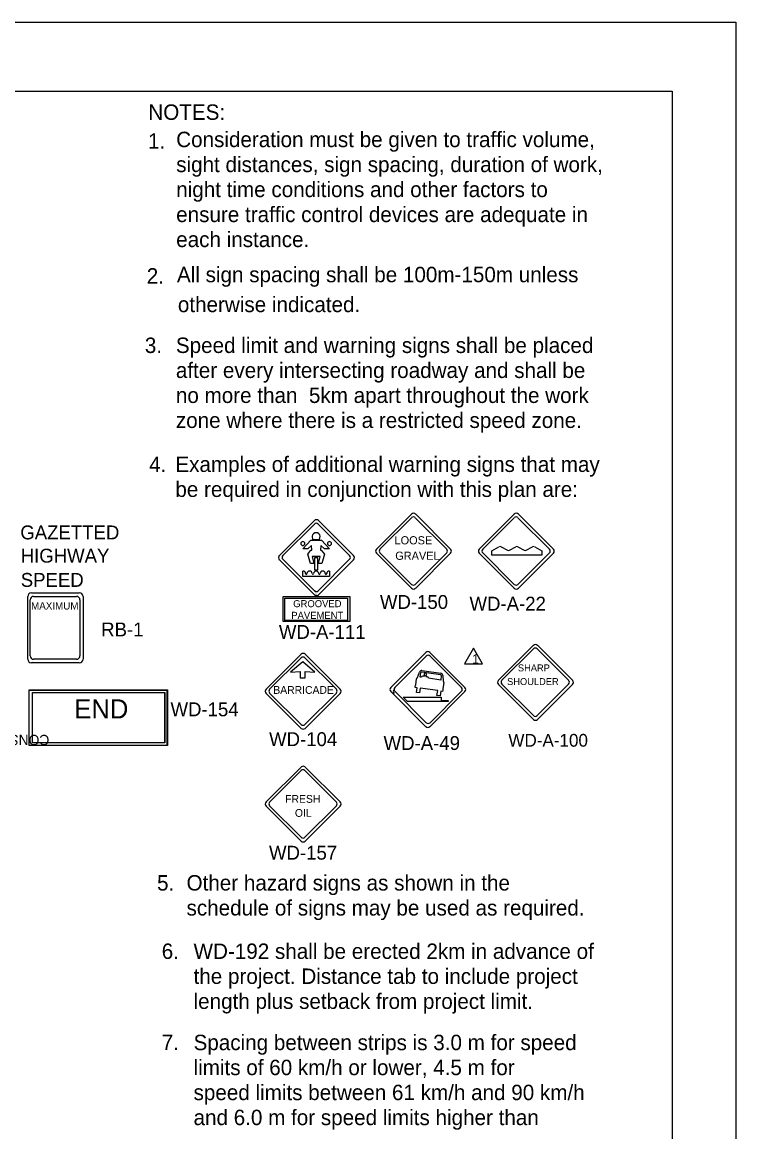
# Model space of a CAD drawing. Extents: x 1372 to 1588, y 125 to 404.
# Drawn here: x 1476.2 to 1588.1, y 229.9 to 404 of the extents above; entities that cross this region are included whole.
import ezdxf

# ---------------------------------------------------------------- set-up
doc = ezdxf.new("R2010")
doc.units = 0
for name, color, linetype in [('Level 1', 7, 'Continuous'), ('Level 10', 7, 'Continuous'), ('Level 2', 7, 'Continuous'), ('Level 4', 7, 'Continuous'), ('Level 44', 7, 'Continuous'), ('Level 5', 7, 'Continuous'), ('Level 60', 7, 'Continuous')]:
    doc.layers.add(name, color=color, linetype=linetype)

msp = doc.modelspace()

# ---------------------------------------------------------------- linework, layer by layer
at = {"layer": 'Level 1'}
for p, q in [((1549.79, 321.06), (1550.93, 321.68)), ((1549.79, 320.37), (1549.79, 321.06)), ((1553.73, 320.37), (1549.79, 320.37)), ((1551.27, 321.68), (1552.25, 321.14)), ((1552.58, 321.14), (1553.56, 321.68)), ((1557.67, 320.37), (1553.73, 320.37)), ((1553.9, 321.68), (1554.87, 321.15)), ((1555.21, 321.15), (1556.19, 321.68)), ((1556.53, 321.68), (1557.67, 321.07)), ((1557.67, 321.07), (1557.67, 320.37)), ((1538.05, 301.1), (1538.16, 301.17)), ((1538.16, 301.17), (1538.47, 302.04)), ((1538.55, 301.26), (1538.7, 301.96)), ((1538.77, 301.22), (1538.55, 301.26)), ((1538.84, 302.28), (1541.83, 301.85)), ((1538.86, 302.06), (1541.75, 301.65)), ((1539.16, 301.38), (1539.01, 301.4)), ((1539.01, 301.4), (1539.01, 301.4)), ((1539.69, 301.3), (1539.54, 301.32)), ((1541.86, 301.51), (1541.83, 300.79)), ((1542.12, 301.53), (1542.17, 300.6)), ((1537.81, 299.62), (1537.81, 299.9)), ((1538.09, 299.59), (1537.81, 299.62)), ((1537.9, 300.03), (1538, 300.99)), ((1537.98, 298.84), (1538.09, 299.59)), ((1538.59, 299.52), (1538.48, 298.77)), ((1541.33, 299.13), (1538.59, 299.52)), ((1541.83, 300.79), (1539.87, 301.07)), ((1542.28, 300.39), (1542.11, 299.42)), ((1542.17, 300.6), (1542.26, 300.5)), ((1538.48, 298.77), (1537.98, 298.84)), ((1541.21, 298.38), (1541.33, 299.13)), ((1541.71, 298.31), (1541.21, 298.38)), ((1541.83, 299.06), (1541.71, 298.31)), ((1542.08, 299.02), (1541.83, 299.05)), ((1542.15, 299.28), (1542.08, 299.02)), ((1542.13, 299.32), (1542.15, 299.28))]:
    msp.add_line(p, q, dxfattribs=at)
for points in [[(1546.94, 305.79), (1545.52, 303.32), (1548.36, 303.32)], [(1542.95, 297.41), (1536.61, 297.41), (1535.92, 298.1), (1541.86, 298.1), (1541.86, 297.58), (1542.95, 297.58)]]:
    msp.add_lwpolyline(points, close=True, dxfattribs=at)
for centre, radius, start, end in [((1551.1, 321.37), 0.35, 61.3649, 118.2462), ((1552.41, 321.45), 0.35, 241.3895, 298.4822), ((1553.73, 321.37), 0.35, 61.6364, 118.4879), ((1555.04, 321.46), 0.35, 241.6262, 298.2462), ((1556.36, 321.37), 0.35, 61.8639, 118.2174), ((1538.79, 301.93), 0.344, 81.9388, 160.7571), ((1538.84, 301.92), 0.138, 81.9344, 167.2438), ((1538.98, 301.2), 0.206, 81.9281, 171.9074), ((1539.17, 301.45), 0.0688, 261.9205, 351.8582), ((1539.55, 301.39), 0.0688, 171.8828, 261.9459), ((1539.66, 301.1), 0.206, 351.9552, 81.9216), ((1541.73, 301.52), 0.138, 356.6105, 81.9338), ((1541.78, 301.51), 0.344, 3.1113, 81.9386), ((1537.77, 300.04), 0.138, 304.1825, 354.8723), ((1538.13, 300.98), 0.138, 124.8259, 174.8703), ((1542.24, 299.4), 0.138, 169.4858, 215.1975), ((1542.15, 300.41), 0.138, 349.4832, 39.2839), ((1534.81, 298.99), 0.457, 135, 225.0349)]:
    msp.add_arc(centre, radius, start, end, dxfattribs=at)
msp.add_ellipse((1539.39, 301.64), major_axis=(-0.035, -0.256), ratio=0.783636, start_param=0.628057, end_param=5.591652, dxfattribs=at)
at = {"layer": 'Level 2'}
for points in [[(1477.28, 299.25), (1498.94, 299.25), (1498.94, 290.55), (1477.28, 290.55)], [(1477.28, 299.22), (1498.87, 299.22), (1498.87, 290.55), (1477.28, 290.55)], [(1477.79, 298.86), (1498.56, 298.86), (1498.56, 290.95), (1477.79, 290.95)], [(1477.79, 298.83), (1498.5, 298.83), (1498.5, 290.94), (1477.79, 290.94)]]:
    msp.add_lwpolyline(points, close=True, dxfattribs=at)
at = {"layer": 'Level 4'}
for p, q in [((1520.18, 321.35), (1521.42, 322.71)), ((1521.42, 322.71), (1523.11, 322.71)), ((1521.64, 323.36), (1521.72, 322.82)), ((1521.72, 322.82), (1522.81, 322.82)), ((1522.81, 322.82), (1522.89, 323.36)), ((1522.89, 323.36), (1522.89, 323.36)), ((1523.11, 322.71), (1524.36, 321.35)), ((1520.94, 321.35), (1520.18, 321.35)), ((1521.54, 321.92), (1520.94, 321.35)), ((1520.94, 320.54), (1521.45, 321.19)), ((1521.4, 319.05), (1520.94, 320.54)), ((1521.45, 321.19), (1521.6, 321.19)), ((1521.6, 321.19), (1521.54, 321.92)), ((1522.99, 321.92), (1522.93, 321.19)), ((1522.93, 321.19), (1523.08, 321.19)), ((1523.6, 321.35), (1522.99, 321.92)), ((1523.08, 321.19), (1523.6, 320.54)), ((1523.6, 320.54), (1523.14, 319.05)), ((1524.36, 321.35), (1523.6, 321.35)), ((1521.89, 319.05), (1521.4, 319.05)), ((1522.88, 320.16), (1521.66, 320.16)), ((1521.66, 320.16), (1521.89, 319.05)), ((1522.54, 319.94), (1522, 319.94)), ((1522, 319.94), (1522, 318.07)), ((1522.54, 318.07), (1522.54, 319.94)), ((1522.64, 319.05), (1522.88, 320.16)), ((1523.14, 319.05), (1522.64, 319.05)), ((1520.19, 317.05), (1520.19, 317.89)), ((1524.34, 317.05), (1520.19, 317.05)), ((1522, 318.07), (1522.54, 318.07)), ((1524.34, 317.89), (1524.34, 317.05))]:
    msp.add_line(p, q, dxfattribs=at)
for centre, radius, start, end in [((1522.27, 323.27), 0.631, 7.9818, 172.0182), ((1520.18, 322.21), 0.31, 45, 225), ((1520.18, 322.21), 0.31, 45.001, 224.999), ((1520.18, 322.21), 0.31, 224.9986, 45.0014), ((1520.18, 322.21), 0.31, 224.999, 45.001), ((1524.36, 322.21), 0.31, 45, 225), ((1524.36, 322.21), 0.31, 45.001, 224.999), ((1524.36, 322.21), 0.31, 224.9986, 45.0014), ((1524.36, 322.21), 0.31, 224.999, 45.001), ((1520.72, 317.48), 0.109, 180, 0), ((1521.75, 317.48), 0.109, 180, 0), ((1522.27, 317.48), 0.407, 0.7691, 179.2309), ((1522.78, 317.48), 0.109, 180, 0), ((1523.3, 317.48), 0.407, 0.7691, 179.2309), ((1523.81, 317.48), 0.109, 180, 0), ((1524.33, 317.48), 0.407, 88.4721, 179.2361)]:
    msp.add_arc(centre, radius, start, end, dxfattribs=at)
for centre, end_param in [((1520.2, 317.48), 4.739059), ((1521.23, 317.48), 6.283185)]:
    msp.add_ellipse(centre, major_axis=(-0.407, 0), ratio=0.986667, start_param=3.141593, end_param=end_param, dxfattribs=at)
at = {"layer": 'Level 44'}
for p, q in [((1521.99, 325.8), (1516.5, 320.32)), ((1528.12, 320.32), (1522.64, 325.8)), ((1537.22, 326.81), (1531.72, 321.33)), ((1532.27, 321.32), (1537.22, 326.26)), ((1537.8, 326.26), (1542.74, 321.32)), ((1543.35, 321.33), (1537.87, 326.81)), ((1553.33, 326.81), (1547.83, 321.33)), ((1548.38, 321.32), (1553.33, 326.26)), ((1553.91, 326.26), (1558.85, 321.32)), ((1559.46, 321.33), (1553.98, 326.81)), ((1517.05, 320.31), (1521.99, 325.25)), ((1522.57, 325.25), (1527.51, 320.31)), ((1531.72, 320.68), (1537.22, 315.19)), ((1531.73, 320.68), (1531.72, 320.68)), ((1537.22, 315.8), (1532.27, 320.74)), ((1542.74, 320.74), (1537.8, 315.8)), ((1537.87, 315.19), (1543.35, 320.68)), ((1547.83, 320.68), (1553.33, 315.19)), ((1547.84, 320.68), (1547.83, 320.68)), ((1553.33, 315.8), (1548.38, 320.74)), ((1558.85, 320.74), (1553.91, 315.8)), ((1553.98, 315.19), (1559.46, 320.68)), ((1516.5, 319.67), (1521.99, 314.18)), ((1516.5, 319.67), (1516.5, 319.67)), ((1521.99, 314.79), (1517.05, 319.73)), ((1527.51, 319.73), (1522.57, 314.79)), ((1522.64, 314.18), (1528.12, 319.67)), ((1477.05, 304.08), (1477.05, 313.88)), ((1477.43, 304.57), (1477.43, 313.39)), ((1477.63, 314.46), (1485.14, 314.46)), ((1477.95, 313.92), (1484.72, 313.92)), ((1485.24, 313.39), (1485.24, 304.57)), ((1485.72, 313.88), (1485.72, 304.08)), ((1519.92, 304.84), (1514.42, 299.35)), ((1526.05, 299.35), (1520.57, 304.84)), ((1539.45, 305.11), (1533.96, 299.63)), ((1545.59, 299.63), (1540.1, 305.11)), ((1556.33, 306.24), (1550.83, 300.75)), ((1551.38, 300.75), (1556.33, 305.68)), ((1556.91, 305.68), (1561.85, 300.75)), ((1562.46, 300.75), (1556.98, 306.24)), ((1477.05, 304.07), (1477.05, 304.08)), ((1477.43, 304.57), (1477.43, 304.57)), ((1485.14, 303.5), (1477.63, 303.5)), ((1477.76, 303.74), (1477.76, 303.74)), ((1484.72, 304.05), (1477.95, 304.05)), ((1514.97, 299.35), (1519.92, 304.29)), ((1514.97, 299.35), (1519.92, 304.29)), ((1514.97, 299.35), (1519.92, 304.29)), ((1520.16, 303.64), (1518.27, 302.05)), ((1520.16, 303.64), (1518.27, 302.05)), ((1520.16, 303.64), (1518.27, 302.05)), ((1522.05, 302.05), (1520.16, 303.64)), ((1522.05, 302.05), (1520.16, 303.64)), ((1522.05, 302.05), (1520.16, 303.64)), ((1520.5, 304.29), (1525.44, 299.35)), ((1520.5, 304.29), (1525.44, 299.35)), ((1520.5, 304.29), (1525.44, 299.35)), ((1534.6, 299.62), (1539.54, 304.56)), ((1540.12, 304.56), (1545.06, 299.62)), ((1518.27, 302.05), (1519.78, 302.13)), ((1518.27, 302.05), (1519.78, 302.13)), ((1518.27, 302.05), (1519.78, 302.13)), ((1519.78, 302.13), (1519.78, 301.12)), ((1519.78, 302.13), (1519.78, 301.12)), ((1519.78, 302.13), (1519.78, 301.12)), ((1519.78, 301.12), (1520.53, 301.12)), ((1519.78, 301.12), (1520.53, 301.12)), ((1519.78, 301.12), (1520.53, 301.12)), ((1520.54, 301.12), (1520.54, 302.13)), ((1520.54, 302.13), (1522.05, 302.05)), ((1520.54, 301.12), (1520.54, 302.13)), ((1520.54, 302.13), (1522.05, 302.05)), ((1520.54, 301.12), (1520.54, 302.13)), ((1520.54, 302.13), (1522.05, 302.05)), ((1539.23, 301.44), (1539.24, 301.46)), ((1539.48, 301.42), (1539.48, 301.41)), ((1537.84, 299.92), (1537.81, 299.9)), ((1550.83, 300.1), (1556.33, 294.61)), ((1550.84, 300.1), (1550.83, 300.1)), ((1556.33, 295.22), (1551.38, 300.16)), ((1561.85, 300.16), (1556.91, 295.22)), ((1556.98, 294.61), (1562.46, 300.1)), ((1514.1, 299.03), (1514.1, 299.03)), ((1514.1, 299.03), (1514.1, 299.03)), ((1514.42, 298.7), (1519.92, 293.21)), ((1514.43, 298.7), (1514.42, 298.7)), ((1519.92, 293.82), (1514.97, 298.76)), ((1519.92, 293.82), (1514.97, 298.76)), ((1519.92, 293.82), (1514.97, 298.76)), ((1525.44, 298.76), (1520.5, 293.82)), ((1525.44, 298.76), (1520.5, 293.82)), ((1525.44, 298.76), (1520.5, 293.82)), ((1520.57, 293.21), (1526.05, 298.7)), ((1533.96, 298.98), (1539.45, 293.48)), ((1533.96, 298.98), (1533.96, 298.98)), ((1539.54, 294.09), (1534.6, 299.04)), ((1540.1, 293.48), (1545.59, 298.98)), ((1545.06, 299.04), (1540.12, 294.09)), ((1542.39, 298.62), (1542.39, 298.62)), ((1519.92, 287.15), (1514.42, 281.67)), ((1514.97, 281.66), (1519.92, 286.6)), ((1520.5, 286.6), (1525.44, 281.66)), ((1526.05, 281.67), (1520.57, 287.15)), ((1514.42, 281.01), (1519.92, 275.52)), ((1514.43, 281.01), (1514.42, 281.01)), ((1519.92, 276.13), (1514.97, 281.07)), ((1525.44, 281.07), (1520.5, 276.13)), ((1520.57, 275.52), (1526.05, 281.01))]:
    msp.add_line(p, q, dxfattribs=at)
msp.add_lwpolyline([(1542.28, 300.38), (1542.29, 300.38)], dxfattribs=at)
for centre, radius, start, end in [((1522.31, 325.48), 0.459, 45, 135), ((1537.54, 326.49), 0.459, 45, 135), ((1537.51, 325.97), 0.413, 45, 135), ((1553.65, 326.49), 0.459, 45, 135), ((1553.62, 325.97), 0.413, 45, 135), ((1522.28, 324.96), 0.413, 45, 135), ((1516.82, 319.99), 0.459, 135, 225), ((1517.34, 320.02), 0.413, 135, 225), ((1527.22, 320.02), 0.413, 315, 45), ((1527.8, 319.99), 0.459, 315, 45), ((1532.05, 321), 0.459, 135, 225), ((1532.57, 321.03), 0.413, 135, 225), ((1542.45, 321.03), 0.413, 315, 45), ((1543.03, 321), 0.459, 315, 45), ((1548.16, 321), 0.459, 135, 225), ((1548.68, 321.03), 0.413, 135, 225), ((1558.56, 321.03), 0.413, 315, 45), ((1559.14, 321), 0.459, 315, 45), ((1537.51, 316.09), 0.413, 225, 315), ((1537.54, 315.51), 0.459, 225, 315), ((1553.62, 316.09), 0.413, 225, 315), ((1553.65, 315.51), 0.459, 225, 315), ((1477.63, 313.88), 0.58, 90, 180), ((1477.96, 313.39), 0.522, 90, 180), ((1484.72, 313.39), 0.522, 360, 90), ((1485.14, 313.88), 0.58, 360, 90), ((1522.28, 315.08), 0.413, 225, 315), ((1522.31, 314.5), 0.459, 225, 315), ((1556.65, 305.91), 0.459, 45, 135), ((1520.24, 304.52), 0.459, 45, 135), ((1539.77, 304.79), 0.459, 45, 135), ((1539.83, 304.27), 0.413, 45, 135), ((1556.62, 305.39), 0.413, 45, 135), ((1477.63, 304.07), 0.58, 180, 270), ((1477.96, 304.57), 0.522, 180, 270), ((1484.72, 304.57), 0.522, 270, 360), ((1485.14, 304.07), 0.58, 270, 360), ((1520.21, 303.99), 0.413, 45, 135), ((1520.21, 303.99), 0.413, 45, 135), ((1520.21, 303.99), 0.413, 45, 135), ((1534.28, 299.3), 0.459, 135, 225), ((1534.89, 299.33), 0.413, 135, 225), ((1544.77, 299.33), 0.413, 315, 45), ((1545.26, 299.3), 0.459, 315, 45), ((1551.16, 300.42), 0.459, 135, 225), ((1551.68, 300.45), 0.413, 135, 225), ((1561.56, 300.45), 0.413, 315, 45), ((1562.14, 300.42), 0.459, 315, 45), ((1514.75, 299.03), 0.459, 135, 225), ((1515.27, 299.06), 0.413, 135, 225), ((1515.27, 299.06), 0.413, 135, 225), ((1515.27, 299.06), 0.413, 135, 225), ((1525.15, 299.06), 0.413, 315, 45), ((1525.15, 299.06), 0.413, 315, 45), ((1525.15, 299.06), 0.413, 315, 45), ((1525.73, 299.03), 0.459, 315, 45), ((1556.62, 295.51), 0.413, 225, 315), ((1556.65, 294.94), 0.459, 225, 315), ((1520.21, 294.12), 0.413, 225, 315), ((1520.21, 294.12), 0.413, 225, 315), ((1520.21, 294.12), 0.413, 225, 315), ((1520.24, 293.54), 0.459, 225, 315), ((1539.77, 293.81), 0.459, 225, 315), ((1539.83, 294.39), 0.413, 225, 315), ((1520.24, 286.83), 0.459, 45, 135), ((1520.21, 286.31), 0.413, 45, 135), ((1514.75, 281.34), 0.459, 135, 225), ((1515.27, 281.37), 0.413, 135, 225), ((1525.15, 281.37), 0.413, 315, 45), ((1525.73, 281.34), 0.459, 315, 45), ((1520.21, 276.43), 0.413, 225, 315), ((1520.24, 275.85), 0.459, 225, 315)]:
    msp.add_arc(centre, radius, start, end, dxfattribs=at)
at = {"layer": 'Level 5'}
for p, q in [((1522.08, 314.76), (1522.13, 314.76)), ((1522.13, 314.76), (1522.08, 314.76)), ((1522.13, 314.76), (1522.13, 314.76)), ((1522.24, 314.22), (1522.29, 314.22)), ((1522.29, 314.22), (1522.24, 314.22)), ((1522.29, 314.22), (1522.29, 314.22))]:
    msp.add_line(p, q, dxfattribs=at)
for points in [[(1517.08, 313.88), (1527.54, 313.88), (1527.54, 309.97), (1517.08, 309.97)], [(1517.36, 313.66), (1527.19, 313.66), (1527.19, 310.14), (1517.36, 310.14)]]:
    msp.add_lwpolyline(points, close=True, dxfattribs=at)
for centre in [(1522.1, 314.79), (1522.27, 314.25)]:
    msp.add_arc(centre, 0.0341, 225, 315, dxfattribs=at)
at = {"layer": 'Level 60'}
for points in [[(1372.06, 403.98), (1588.06, 403.98), (1588.06, 124.98), (1372.06, 124.98)], [(1391.18, 393.17), (1578.06, 393.17), (1578.06, 135.79), (1391.18, 135.79)]]:
    msp.add_lwpolyline(points, close=True, dxfattribs=at)

# ---------------------------------------------------------------- texts
at = {"layer": 'Level 1'}
msp.add_text('1', height=1.45, rotation=360, dxfattribs=at).set_placement((1546.72, 303.38))
at = {"layer": 'Level 10'}
for s, height, p in [('NOTES:', 2.419, (1495.96, 388.66)), ('1.', 2.419, (1495.91, 384.14)), ('Consideration must be given to traffic volume,', 2.419, (1500.33, 384.38)), ('sight distances, sign spacing, duration of work,', 2.419, (1500.33, 380.46)), ('night time conditions and other factors to', 2.419, (1500.33, 376.54)), ('ensure traffic control devices are adequate in', 2.419, (1500.33, 372.62)), ('each instance.', 2.419, (1500.33, 368.7)), ('All sign spacing shall be 100m-150m unless', 2.419, (1500.45, 363.19)), ('2.', 2.419, (1495.71, 362.98)), ('otherwise indicated.', 2.419, (1500.59, 358.5)), ('3.', 2.419, (1495.41, 352.09)), ('Speed limit and warning signs shall be placed ', 2.419, (1500.28, 352.09)), ('after every intersecting roadway and shall be ', 2.419, (1500.28, 348.17)), ('no more than  5km apart throughout the work ', 2.419, (1500.28, 344.25)), ('zone where there is a restricted speed zone.', 2.419, (1500.28, 340.33)), ('Examples of additional warning signs that may', 2.419, (1500.2, 333.43)), ('4.', 2.419, (1496.08, 333.4)), ('be required in conjunction with this plan are:', 2.419, (1500.2, 329.51)), ('WD-A-49', 2.178, (1532.84, 289.82)), ('5.', 2.419, (1497.33, 267.77)), ('Other hazard signs as shown in the', 2.419, (1501.95, 267.78)), ('schedule of signs may be used as required.       ', 2.419, (1501.95, 263.86)), ('6.', 2.419, (1498.06, 257.05)), ('WD-192 shall be erected 2km in advance of ', 2.419, (1503.05, 257.05)), ('the project. Distance tab to include project ', 2.419, (1503.05, 253.13)), ('length plus setback from project limit.', 2.419, (1503.05, 249.21)), ('7.', 2.419, (1498.06, 242.74)), ('Spacing between strips is 3.0 m for speed', 2.419, (1503.05, 242.74)), ('limits of 60 km/h or lower, 4.5 m for', 2.419, (1503.05, 238.82)), ('speed limits between 61 km/h and 90 km/h', 2.419, (1503.05, 234.9)), ('and 6.0 m for speed limits higher than', 2.419, (1503.05, 230.98))]:
    msp.add_text(s, height=height, dxfattribs=at).set_placement(p)
for s, p in [('GAZETTED', (1475.89, 322.86)), ('HIGHWAY', (1475.95, 319.21)), ('SPEED', (1475.96, 315.41)), ('WD-150', (1532.27, 311.95)), ('WD-A-22', (1546.31, 311.68)), ('RB-1', (1488.57, 307.64)), ('WD-A-111', (1516.43, 307.25)), ('WD-154', (1499.44, 295.11)), ('WD-104', (1514.89, 290.43)), ('WD-157', (1514.88, 272.62))]:
    msp.add_text(s, height=2.177, rotation=360, dxfattribs=at).set_placement(p)
at = {"layer": 'Level 44'}
for s, height, rotation, p in [('LOOSE', 1.282, 360, (1534.56, 322.07)), ('GRAVEL', 1.282, 360, (1534.67, 319.65)), ('MAXIMUM', 1.15, 360, (1477.58, 311.85)), ('BARRICADE', 1.218, 360, (1515.55, 298.63)), ('BARRICADE', 1.218, 360, (1515.55, 298.63)), ('BARRICADE', 1.218, 360, (1515.55, 298.63)), ('END', 3, 360, (1484.36, 294.77)), ('CONSTRUCTION', 1.62, 180, (1480.44, 292.2))]:
    msp.add_text(s, height=height, rotation=rotation, dxfattribs=at).set_placement(p)
for s, height, p in [('SHARP', 1.089, (1553.9, 302.15)), ('SHOULDER', 1.089, (1552.2, 300.01)), ('WD-A-100      ', 1.999, (1552.4, 290.34)), ('FRESH', 1.218, (1517.41, 281.54)), ('OIL', 1.218, (1518.94, 279.34))]:
    msp.add_text(s, height=height, dxfattribs=at).set_placement(p)
at = {"layer": 'Level 5'}
for s, p in [('GROOVED', (1518.67, 312.22)), ('PAVEMENT', (1518.37, 310.39))]:
    msp.add_text(s, height=1.108, dxfattribs=at).set_placement(p)

doc.saveas('drawing.dxf')
